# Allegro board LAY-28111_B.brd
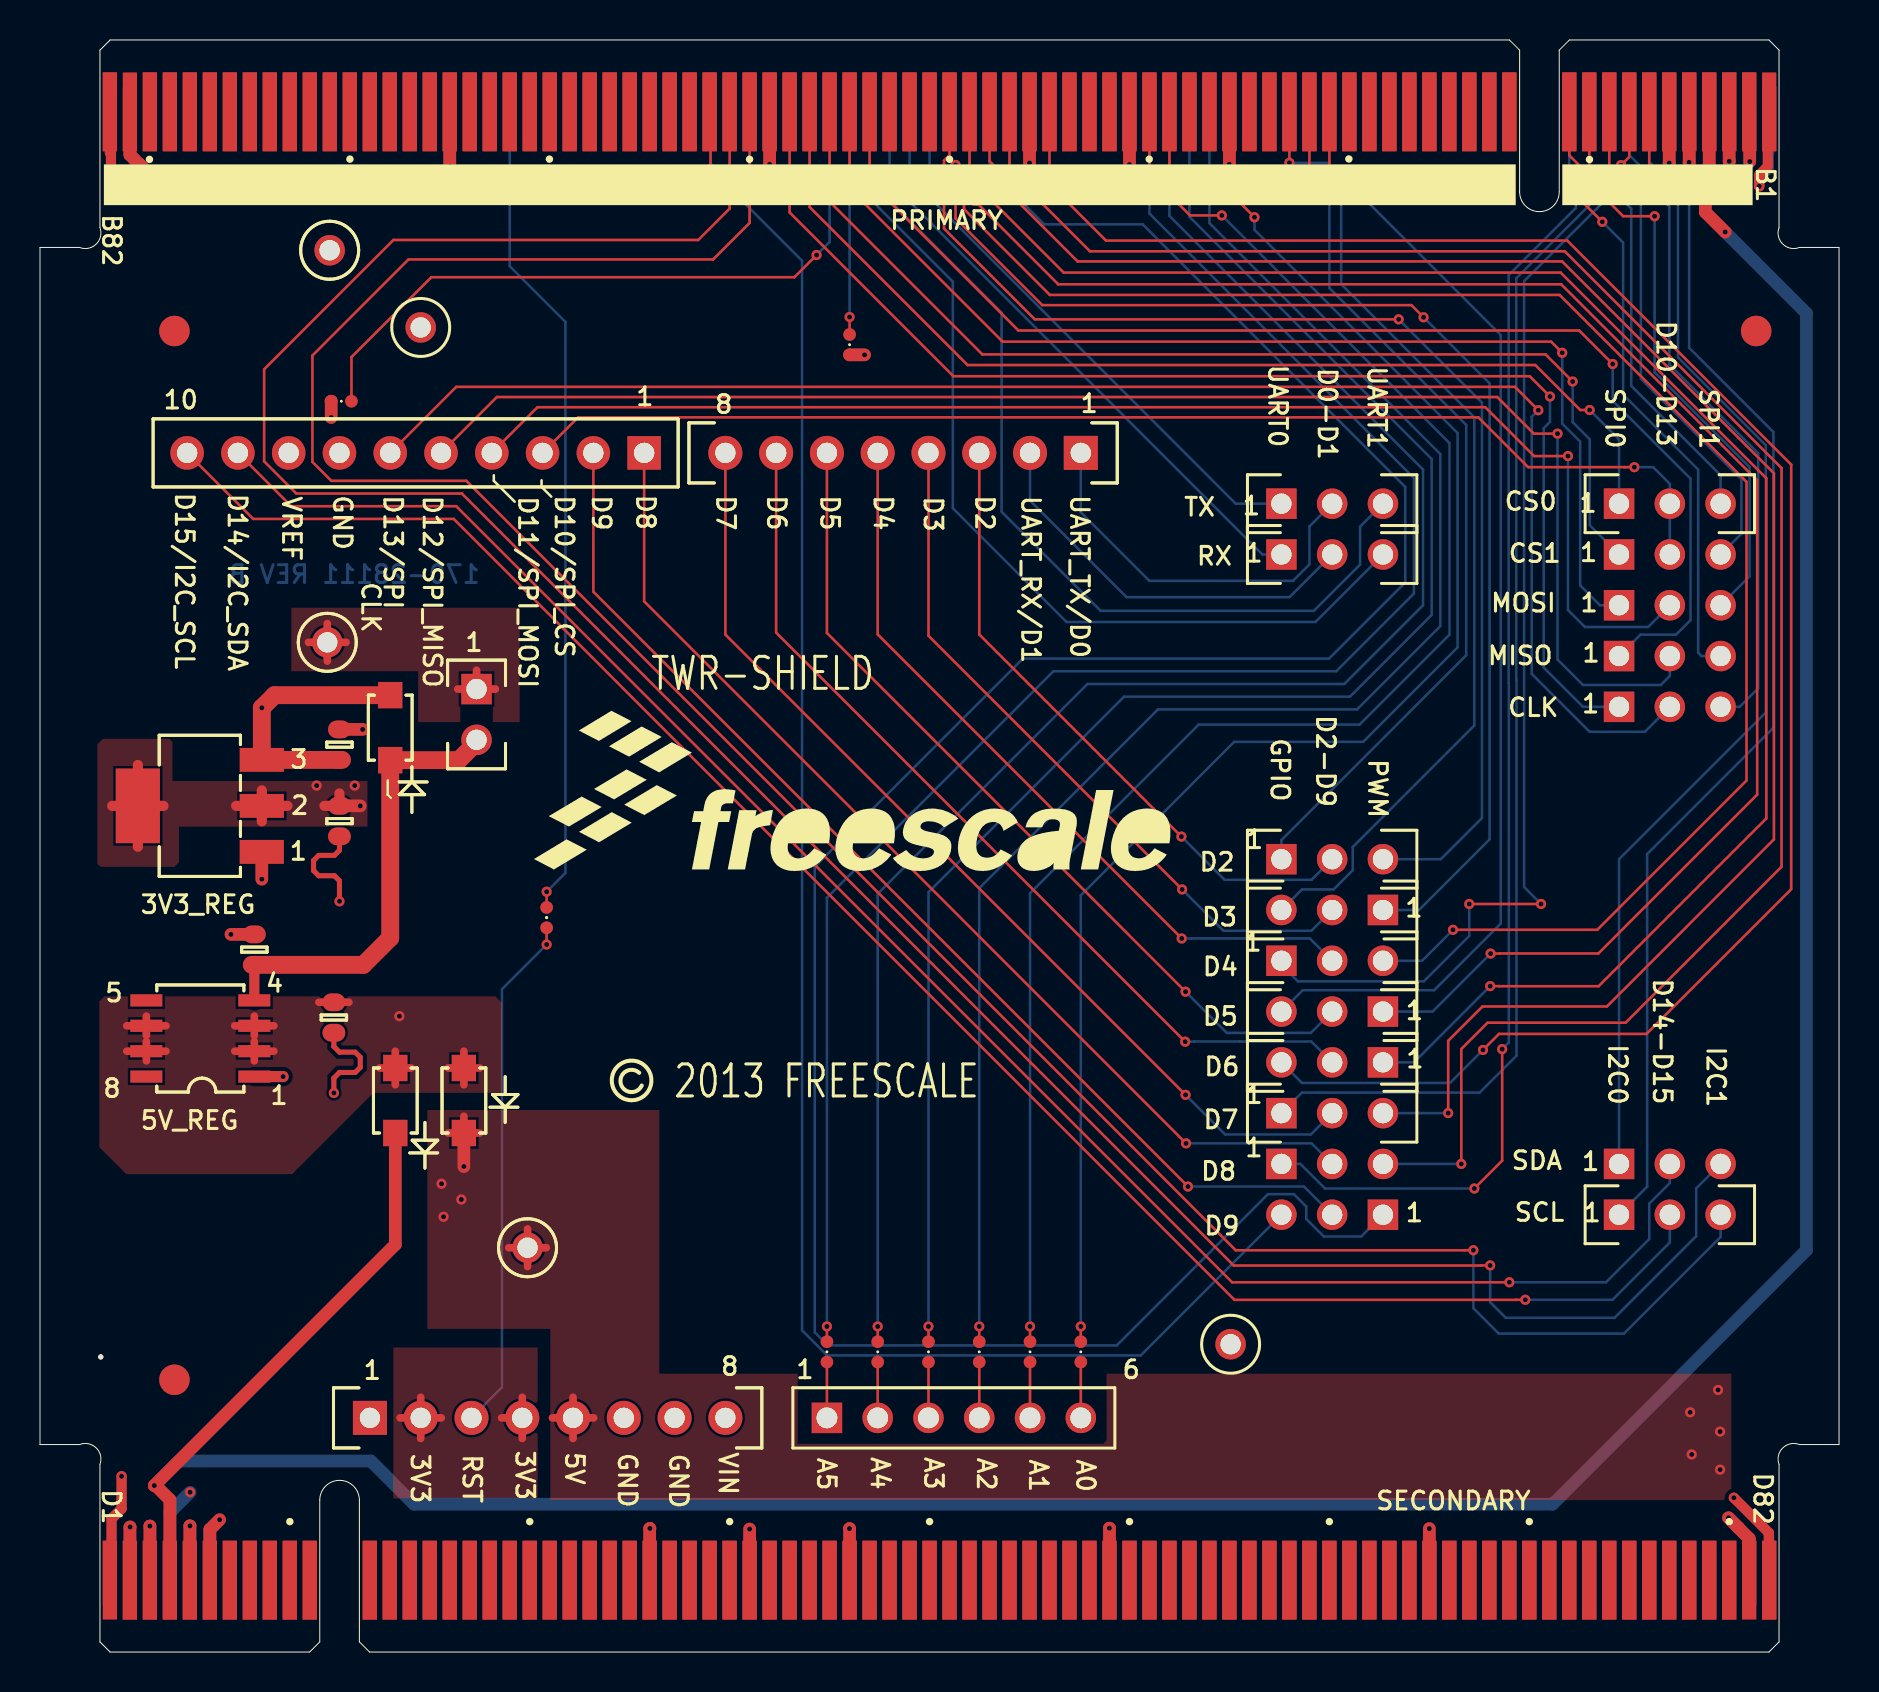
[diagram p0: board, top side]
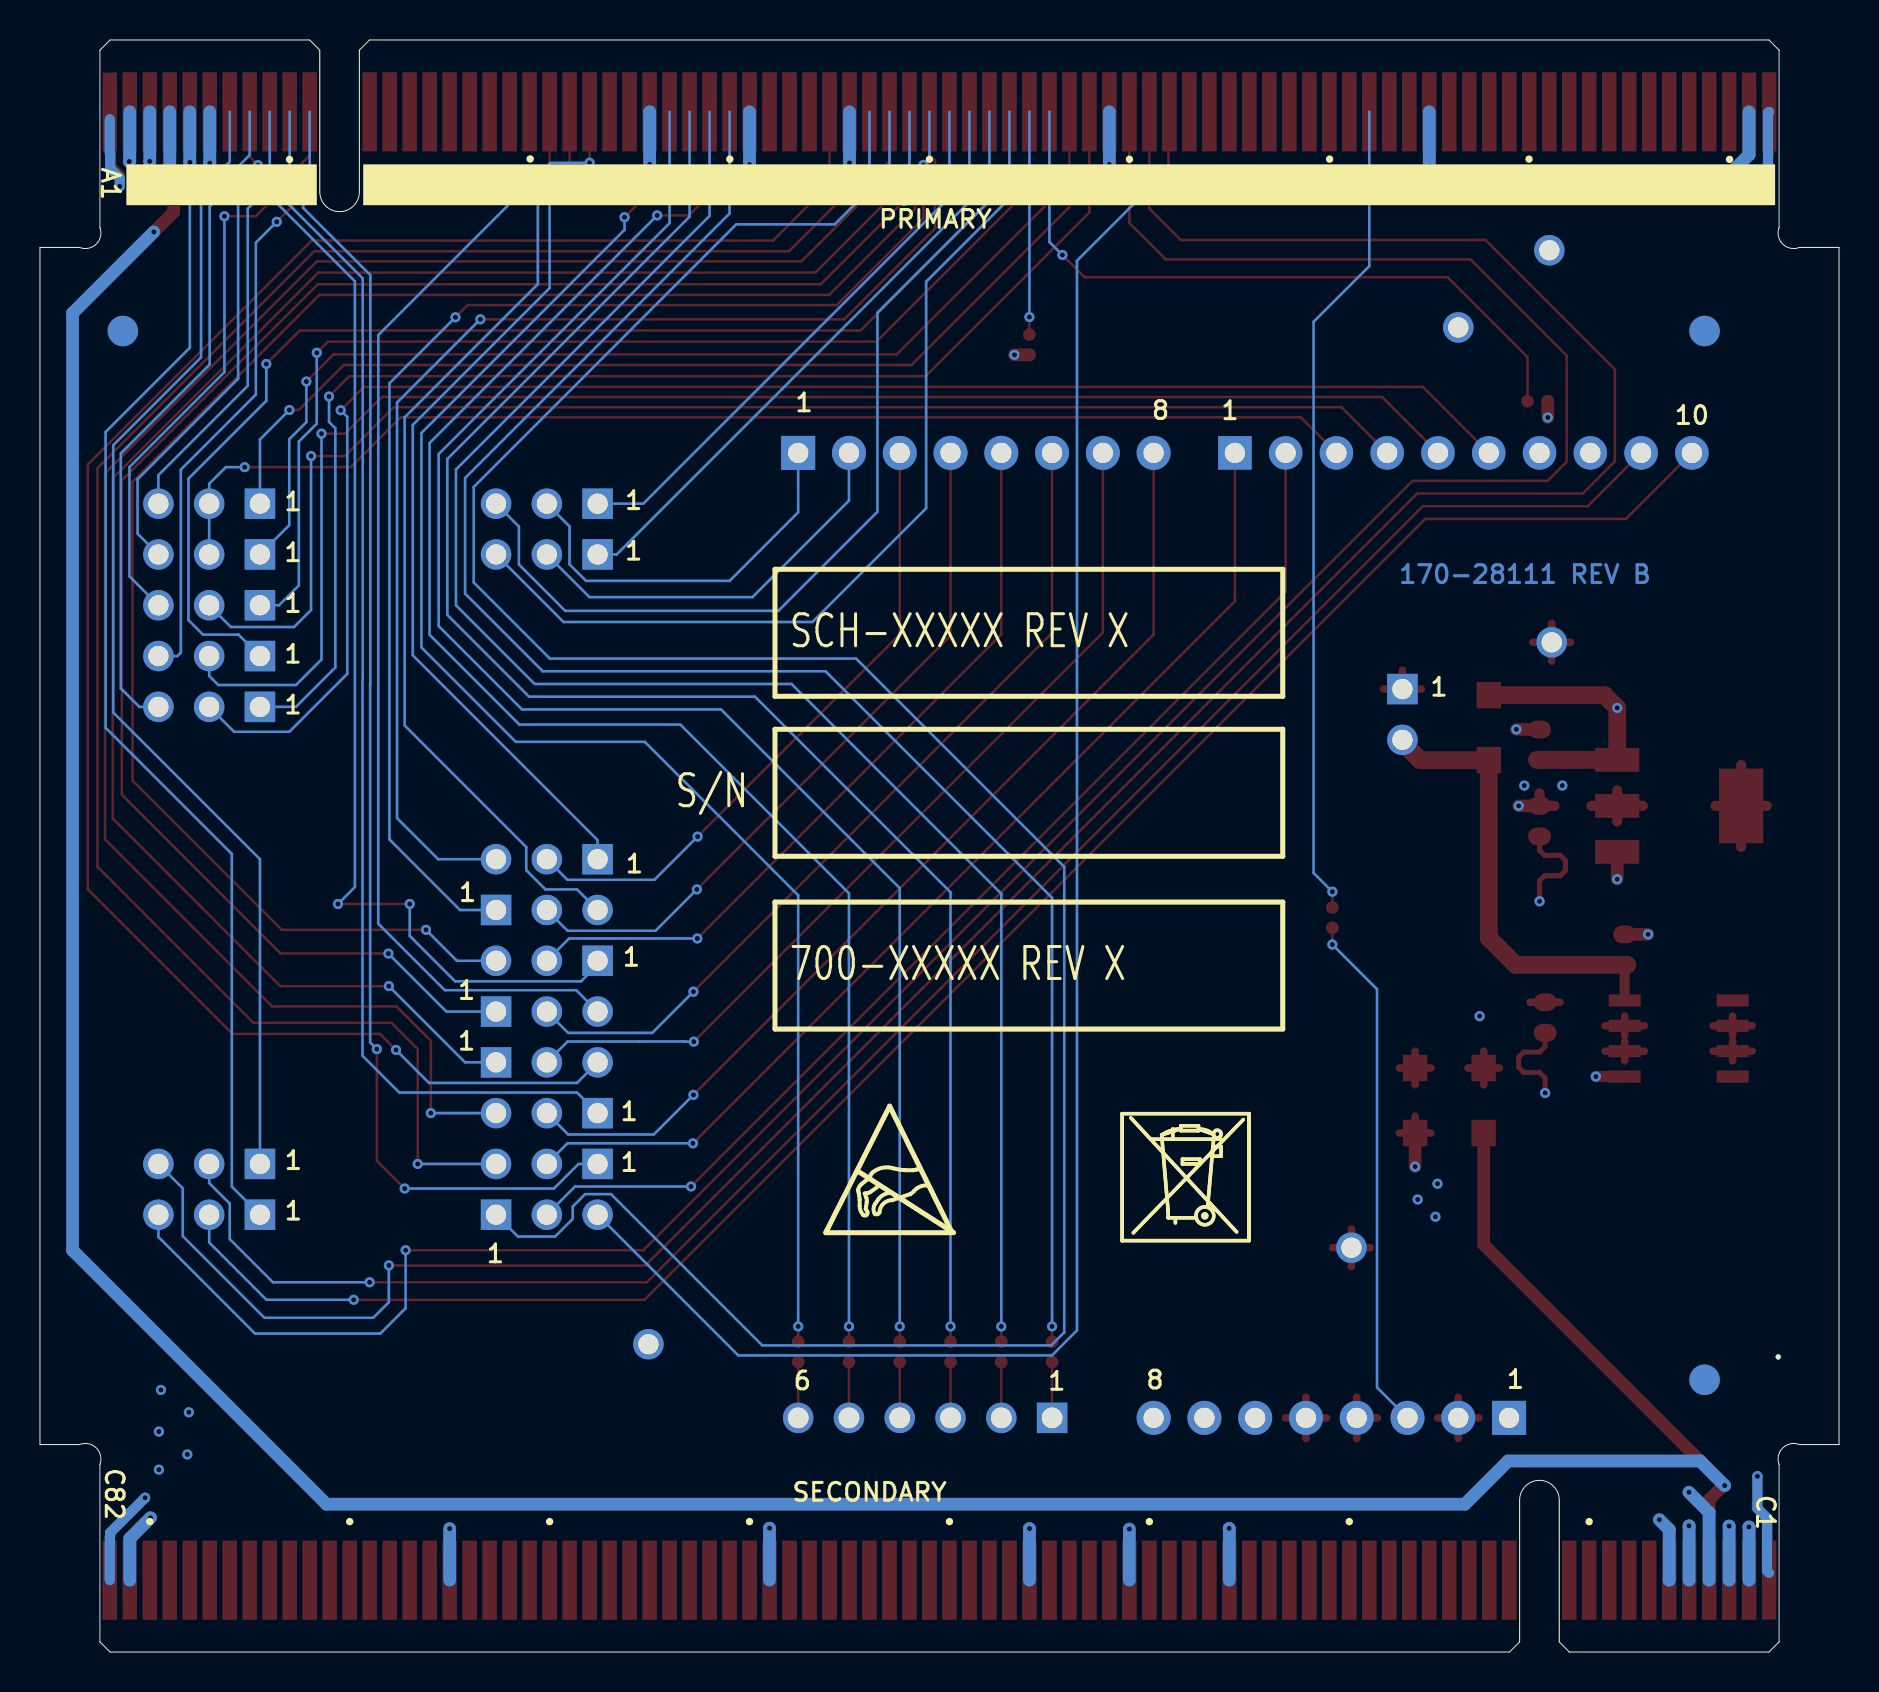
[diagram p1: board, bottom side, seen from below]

Outline 89.99 x 80.62 mm; copper layers: TOP, L2_GND, L3_PWR, BOTTOM. Coordinates in mm from the lower left corner of the outline.
Outline path: 0,70.24 0,10.38 1.98,10.38 arc(2.82,10.21) 3,9.37 3,0.51 3.51,0 13.49,0 14,0.51 14,7.59 arc(14.99,8.59) 15.98,7.59 15.98,0.51 16.48,0 86.49,0 86.99,0.51 86.99,9.37 arc(87.18,10.21) 88.01,10.38 89.99,10.38 89.99,70.24 88.01,70.24 arc(87.18,70.41) 86.99,71.25 86.99,80.11 86.49,80.62 76.5,80.62 76,80.11 76,73.03 arc(75.01,72.03) 74.02,73.03 74.02,80.11 73.51,80.62 3.51,80.62 3,80.11 3,71.25 arc(2.82,70.41) 1.98,70.24 0,70.24

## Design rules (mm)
net group POWER: nets ELE_PS_SENSE GND VIN_HDR VIN_HDR_D

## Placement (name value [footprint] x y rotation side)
C2  10uF  [CC0603_OV]  14.98 41.55 270 top
C4  10uF  [CC0603_OV]  14.98 45.38 90 top
C5  10uF  [CC0603_OV]  14.7 31.73 270 top
C6  10uF  [CC0603_OV]  10.72 35.13 90 top
D12  MBR120VLSFT1G  [SOD-123]  17.52 46.23 90 top
D15  MBR120VLSFT1G  [SOD-123]  21.2 27.58 270 top
D16  MBR120VLSFT1G  [SOD-123]  17.77 27.58 270 top
J1  CON_1X8  [CON_1X8_SKT_2P54_TH]  52.06 59.97 270 top
J2  CON_1X10  [HDR110]  30.22 59.97 270 top
J3  CON_1X6  [CON_SKT1X6_TH]  39.36 11.71 90 top
J4  CON_1X8  [CON_1X8_SKT_2P54_TH]  16.5 11.71 90 top
J16  PCI EXPRESS TOWER SYSTEM  [CN2X82_FINGER_ASS]  3 14.76 0 top
J20  HDR 1X2 TH  [SH_HDR102_BOTTOM]  21.84 48.16 0 top
J63  HDR 1x3 TH  [HDR103_SHORT1_2]  62.1 54.89 90 top
J64  HDR 1x3 TH  [HDR103_SHORT1_2]  78.99 24.41 90 top
J65  HDR 1x3 TH  [HDR103_SHORT1_2]  78.99 47.27 90 top
J66  HDR 1x3 TH  [HDR103_SHORT1_2]  78.99 21.87 90 top
J67  HDR 1x3 TH  [HDR103_SHORT1_2]  62.1 57.43 90 top
J68  HDR 1x3 TH  [HDR103_SHORT1_2]  67.18 37.11 270 top
J69  HDR 1x3 TH  [HDR103_SHORT1_2]  62.1 34.57 90 top
J70  HDR_1X3  [HDR103]  78.99 54.89 90 top
J71  HDR 1x3 TH  [HDR103_SHORT1_2]  67.18 21.87 270 top
J72  HDR 1x3 TH  [HDR103_SHORT1_2]  62.1 39.65 90 top
J73  HDR 1x3 TH  [HDR103_SHORT1_2]  78.99 52.35 90 top
J74  HDR 1x3 TH  [HDR103_SHORT1_2]  78.99 57.43 90 top
J78  HDR 1x3 TH  [HDR103_SHORT1_2]  67.18 32.03 270 top
J80  HDR 1x3 TH  [HDR103_SHORT1_2]  67.18 29.49 270 top
J81  HDR 1x3 TH  [HDR103_SHORT1_2]  78.99 49.81 90 top
J82  HDR 1x3 TH  [HDR103_SHORT1_2]  62.1 24.41 90 top
J83  HDR 1x3 TH  [HDR103_SHORT1_2]  62.1 26.95 90 top
NOREF  -  [unnamed]  3.04 14.76 0 top
NOREF#2  -  [#2]  5.02 37.18 0 top
NOREF#3  -  [#2]  51.86 -0.01 0 top
NOREF#4  -  [unnamed]  6.73 66.07 0 top
NOREF#5  -  [#2]  4.54 3.59 0 top
NOREF#6  -  [#2]  27.68 59.97 0 top
NOREF#7  -  [#2]  50.67 130.33 0 top
NOREF#8  -  [unnamed]  6.73 13.61 0 top
NOREF#9  -  [#2]  -93.48 -190.35 0 top
NOREF#10  -  [#2]  -3.94 -37.31 0 top
NOREF#11  -  [#2]  29.72 28.71 0 top
NOREF#12  -  [#2]  24.71 39.55 0 top
NOREF#13  -  [#2]  -88.4 146.2 0 top
NOREF#14  -  [#2]  0.05 70.23 0 top
NOREF#15  -  [#2]  87.04 80.11 0 top
NOREF#16  -  [#2]  10.72 28.78 90 top
NOREF#17  -  [#2]  5.32 28.78 0 top
NOREF#18  -  [#2]  35.1 80.63 0 top
NOREF#19  -  [#2]  0.05 10.39 90 top
NOREF#20  -  [#2]  -409.71 -287.38 0 top
NOREF#21  -  [#2]  10.02 33.18 90 top
NOREF#22  -  [#2]  0.05 10.38 90 top
NOREF#23  -  [#2]  90.04 10.38 90 top
NOREF#24  -  [#2]  0.05 10.39 90 top
NOREF#25  -  [#2]  3.04 14.76 0 top
NOREF#26  -  [#2]  86.53 0 90 top
NOREF#27  -  [#2]  16.02 0.51 0 top
NOREF#28  -  [#2]  0.05 10.39 90 top
NOREF#29  -  [#2]  184.91 70.26 0 top
NOREF#30  -  [#2]  0.05 10.39 0 top
NOREF#31  -  [#2]  141.23 79.22 0 top
NOREF#32  -  [unnamed]  85.85 66.07 0 top
NOREF#33  -  [#2]  3.04 14.76 0 top
NOREF#34  -  [#2]  75.06 88.58 0 top
NOREF#35  -  [#2]  0.05 10.39 90 top
NOREF#36  -  [#2]  200.15 4.85 0 top
NOREF#37  -  [#2]  79.88 10.95 0 top
NOREF#38  -  [#2]  5.54 77.03 0 top
NOREF#39  -  [#2]  168.27 -55.73 0 top
NOREF#40  -  [#2]  3.04 0.51 0 top
NOREF#41  -  [#2]  -378.59 230.02 0 top
NOREF#42  -  [#2]  2.27 15.54 0 top
NOREF#43  -  [#2]  3.55 0 90 top
NOREF#44  -  [unnamed]  85.85 66.07 180 bottom
NOREF#45  -  [#2]  53.23 39.8 180 bottom
NOREF#46  -  [#2]  50.67 20.97 180 bottom
NOREF#47  -  [unnamed]  6.73 66.07 180 bottom
NOREF#48  -  [#2]  35.86 20.57 180 bottom
NOREF#49  -  [unnamed]  6.73 13.61 180 bottom
NOREF#50  -  [#2]  53.23 31.16 180 bottom
NOREF#51  -  [#2]  53.23 47.8 180 bottom
NOREF#52  -  [#2]  79.88 10.95 180 bottom
R78  0  [RC0402_25]  15.07 62.55 180 top
R79  0  [RC0402_25]  25.34 36.73 270 top
R80  0  [RC0402_25]  46.98 15.01 270 top
R81  0  [RC0402_25]  44.44 15.01 270 top
R82  0  [RC0402_25]  41.9 15.01 270 top
R83  0  [RC0402_25]  39.36 15.01 270 top
R84  0  [RC0402_25]  52.06 15.01 90 top
R85  0  [RC0402_25]  49.52 15.01 90 top
R86  0  [RC0402_25]  40.5 65.38 270 top
TP1  TEST POINT WHITE  [TEST_LOOP]  24.39 20.22 0 top
TP2  TEST POINT WHITE  [TEST_LOOP]  14.37 50.5 0 top
TP3  TEST POINT WHITE  [TEST_LOOP]  14.49 70.1 0 top
TP4  TEST POINT WHITE  [TEST_LOOP]  59.56 15.39 0 top
TP5  TEST POINT WHITE  [TEST_LOOP]  19.04 66.24 0 top
U1  NCP1117ST33T3G  [SOT223]  8 42.32 90 top
U2  MC33269DR2-5.0G  [SO8_1P27_4X5]  8.02 30.68 180 top

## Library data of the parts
C2 C4-C6 = CAP_NP
D12 D15 D16 = DIODE_SCHTKY
J1 J4 = CONN_HDR_8X1
J2 = RCPT 1X10
J3 = CONN_HDR_6X1
J16 = CONN_PCI_XPRESS_X16_328P
J20 = CONN_HDR_2X1
J63-J69 J71-J74 J78 J80-J83 = CONN_HDR_3X1_SHORT
J70 = CONN_HDR_3X1
R78-R86 = RES
TP1-TP5 = TestLoop
U1 = LD1117AS18
U2 = MC33269D

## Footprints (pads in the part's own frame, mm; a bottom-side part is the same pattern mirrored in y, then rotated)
CC0603_OV
  oval 0.889x1.143 smd: 1(-0.762,0) 2(0.762,0)
CN2X82_FINGER_ASS
  rect 0.711x3.2 smd: A1(83.499,61.9) B81(1.499,61.9) C1(0.499,-10.795) D81(82.499,-10.795)
  rect 0.711x3.937 smd: A2(82.499,62.268) A3(81.499,62.268) A4(80.499,62.268) A5(79.499,62.268) A6(78.499,62.268) A7(77.499,62.268) A8(76.499,62.268) A9(75.499,62.268) A10(74.499,62.268) A11(73.499,62.268) A12(70.499,62.268) A13(69.499,62.268) A14(68.499,62.268) A15(67.499,62.268) A16(66.499,62.268) A17(65.499,62.268) A18(64.499,62.268) A19(63.499,62.268) A20(62.499,62.268) A21(61.499,62.268) A22(60.499,62.268) A23(59.499,62.268) A24(58.499,62.268) A25(57.499,62.268) A26(56.499,62.268) A27(55.499,62.268) A28(54.499,62.268) A29(53.499,62.268) A30(52.499,62.268) A31(51.499,62.268) A32(50.499,62.268) A33(49.499,62.268) A34(48.499,62.268) A35(47.499,62.268) A36(46.499,62.268) A37(45.499,62.268) A38(44.499,62.268) A39(43.499,62.268) A40(42.499,62.268) A41(41.499,62.268) A42(40.499,62.268) A43(39.499,62.268) A44(38.499,62.268) A45(37.499,62.268) A46(36.499,62.268) A47(35.499,62.268) A48(34.499,62.268) A49(33.499,62.268) A50(32.499,62.268) A51(31.499,62.268) A52(30.499,62.268) A53(29.499,62.268) A54(28.499,62.268) A55(27.499,62.268) A56(26.499,62.268) A57(25.499,62.268) A58(24.499,62.268) A59(23.499,62.268) A60(22.499,62.268) A61(21.499,62.268) A62(20.499,62.268) A63(19.499,62.268) A64(18.499,62.268) A65(17.499,62.268) A66(16.499,62.268) A67(15.499,62.268) A68(14.499,62.268) A69(13.499,62.268) A70(12.499,62.268) A71(11.499,62.268) A72(10.499,62.268) A73(9.499,62.268) A74(8.499,62.268) A75(7.499,62.268) A76(6.499,62.268) A77(5.499,62.268) A78(4.499,62.268) A79(3.499,62.268) A80(2.499,62.268) A81(1.499,62.268) A82(0.499,62.268) B1(83.499,62.268) B2(82.499,62.268) B3(81.499,62.268) B4(80.499,62.268) B5(79.499,62.268) B6(78.499,62.268) B7(77.499,62.268) B8(76.499,62.268) B9(75.499,62.268) B10(74.499,62.268) B11(73.499,62.268) B12(70.499,62.268) B13(69.499,62.268) B14(68.499,62.268) B15(67.499,62.268) B16(66.499,62.268) B17(65.499,62.268) B18(64.499,62.268) B19(63.499,62.268) B20(62.499,62.268) B21(61.499,62.268) B22(60.499,62.268) B23(59.499,62.268) B24(58.499,62.268) B25(57.499,62.268) B26(56.499,62.268) B27(55.499,62.268) B28(54.499,62.268) B29(53.499,62.268) B30(52.499,62.268) B31(51.499,62.268) B32(50.499,62.268) B33(49.499,62.268) B34(48.499,62.268) B35(47.499,62.268) B36(46.499,62.268) B37(45.499,62.268) B38(44.499,62.268) B39(43.499,62.268) B40(42.499,62.268) B41(41.499,62.268) B42(40.499,62.268) B43(39.499,62.268) B44(38.499,62.268) B45(37.499,62.268) B46(36.499,62.268) B47(35.499,62.268) B48(34.499,62.268) B49(33.499,62.268) B50(32.499,62.268) B51(31.499,62.268) B52(30.499,62.268) B53(29.499,62.268) B54(28.499,62.268) B55(27.499,62.268) B56(26.499,62.268) B57(25.499,62.268) B58(24.499,62.268) B59(23.499,62.268) B60(22.499,62.268) B61(21.499,62.268) B62(20.499,62.268) B63(19.499,62.268) B64(18.499,62.268) B65(17.499,62.268) B66(16.499,62.268) B67(15.499,62.268) B68(14.499,62.268) B69(13.499,62.268) B70(12.499,62.268) B71(11.499,62.268) B72(10.499,62.268) B73(9.499,62.268) B74(8.499,62.268) B75(7.499,62.268) B76(6.499,62.268) B77(5.499,62.268) B78(4.499,62.268) B79(3.499,62.268) B80(2.499,62.268) B82(0.499,62.268) C2(1.499,-11.163) C3(2.499,-11.163) C4(3.499,-11.163) C5(4.499,-11.163) C6(5.499,-11.163) C7(6.499,-11.163) C8(7.499,-11.163) C9(8.499,-11.163) C10(9.499,-11.163) C11(10.499,-11.163) C12(13.499,-11.163) C13(14.499,-11.163) C14(15.499,-11.163) C15(16.499,-11.163) C16(17.499,-11.163) C17(18.499,-11.163) C18(19.499,-11.163) C19(20.499,-11.163) C20(21.499,-11.163) C21(22.499,-11.163) C22(23.499,-11.163) C23(24.499,-11.163) C24(25.499,-11.163) C25(26.499,-11.163) C26(27.499,-11.163) C27(28.499,-11.163) C28(29.499,-11.163) C29(30.499,-11.163) C30(31.499,-11.163) C31(32.499,-11.163) C32(33.499,-11.163) C33(34.499,-11.163) C34(35.499,-11.163) C35(36.499,-11.163) C36(37.499,-11.163) C37(38.499,-11.163) C38(39.499,-11.163) C39(40.499,-11.163) C40(41.499,-11.163) C41(42.499,-11.163) C42(43.499,-11.163) C43(44.499,-11.163) C44(45.499,-11.163) C45(46.499,-11.163) C46(47.499,-11.163) C47(48.499,-11.163) C48(49.499,-11.163) C49(50.499,-11.163) C50(51.499,-11.163) C51(52.499,-11.163) C52(53.499,-11.163) C53(54.499,-11.163) C54(55.499,-11.163) C55(56.499,-11.163) C56(57.499,-11.163) C57(58.499,-11.163) C58(59.499,-11.163) C59(60.499,-11.163) C60(61.499,-11.163) C61(62.499,-11.163) C62(63.499,-11.163) C63(64.499,-11.163) C64(65.499,-11.163) C65(66.499,-11.163) C66(67.499,-11.163) C67(68.499,-11.163) C68(69.499,-11.163) C69(70.499,-11.163) C70(71.499,-11.163) C71(72.499,-11.163) C72(73.499,-11.163) C73(74.499,-11.163) C74(75.499,-11.163) C75(76.499,-11.163) C76(77.499,-11.163) C77(78.499,-11.163) C78(79.499,-11.163) C79(80.499,-11.163) C80(81.499,-11.163) C81(82.499,-11.163) C82(83.499,-11.163) D1(0.499,-11.163) D2(1.499,-11.163) D3(2.499,-11.163) D4(3.499,-11.163) D5(4.499,-11.163) D6(5.499,-11.163) D7(6.499,-11.163) D8(7.499,-11.163) D9(8.499,-11.163) D10(9.499,-11.163) D11(10.499,-11.163) D12(13.499,-11.163) D13(14.499,-11.163) D14(15.499,-11.163) D15(16.499,-11.163) D16(17.499,-11.163) D17(18.499,-11.163) D18(19.499,-11.163) D19(20.499,-11.163) D20(21.499,-11.163) D21(22.499,-11.163) D22(23.499,-11.163) D23(24.499,-11.163) D24(25.499,-11.163) D25(26.499,-11.163) D26(27.499,-11.163) D27(28.499,-11.163) D28(29.499,-11.163) D29(30.499,-11.163) D30(31.499,-11.163) D31(32.499,-11.163) D32(33.499,-11.163) D33(34.499,-11.163) D34(35.499,-11.163) D35(36.499,-11.163) D36(37.499,-11.163) D37(38.499,-11.163) D38(39.499,-11.163) D39(40.499,-11.163) D40(41.499,-11.163) D41(42.499,-11.163) D42(43.499,-11.163) D43(44.499,-11.163) D44(45.499,-11.163) D45(46.499,-11.163) D46(47.499,-11.163) D47(48.499,-11.163) D48(49.499,-11.163) D49(50.499,-11.163) D50(51.499,-11.163) D51(52.499,-11.163) D52(53.499,-11.163) D53(54.499,-11.163) D54(55.499,-11.163) D55(56.499,-11.163) D56(57.499,-11.163) D57(58.499,-11.163) D58(59.499,-11.163) D59(60.499,-11.163) D60(61.499,-11.163) D61(62.499,-11.163) D62(63.499,-11.163) D63(64.499,-11.163) D64(65.499,-11.163) D65(66.499,-11.163) D66(67.499,-11.163) D67(68.499,-11.163) D68(69.499,-11.163) D69(70.499,-11.163) D70(71.499,-11.163) D71(72.499,-11.163) D72(73.499,-11.163) D73(74.499,-11.163) D74(75.499,-11.163) D75(76.499,-11.163) D76(77.499,-11.163) D77(78.499,-11.163) D78(79.499,-11.163) D79(80.499,-11.163) D80(81.499,-11.163) D82(83.499,-11.163)
CON_1X8_SKT_2P54_TH
  rect 1.702x1.702 hole 1.016: 1(0,0)
  round 1.702 hole 1.016: 2(0,-2.54) 3(0,-5.08) 4(0,-7.62) 5(0,-10.16) 6(0,-12.7) 7(0,-15.24) 8(0,-17.78)
CON_SKT1X6_TH
  rect 1.524x1.524 hole 1.041: 1(0,0)
  round 1.524 hole 1.041: 2(0,-2.54) 3(0,-5.08) 4(0,-7.62) 5(0,-10.16) 6(0,-12.7)
HDR103
  rect 1.524x1.524 hole 1.016: 1(0,0)
  round 1.524 hole 1.016: 2(0,-2.54) 3(0,-5.08)
HDR103_SHORT1_2
  rect 1.524x1.524 hole 1.016: 1(0,0)
  round 1.524 hole 1.016: 2(0,-2.54) 3(0,-5.08)
HDR110
  rect 1.676x1.676 hole 1.016: 1(0,0)
  round 1.676 hole 1.016: 2(0,-2.54) 3(0,-5.08) 4(0,-7.62) 5(0,-10.16) 6(0,-12.7) 7(0,-15.24) 8(0,-17.78) 9(0,-20.32) 10(0,-22.86)
RC0402_25
  round 0.635 smd: 1(-0.508,0) 2(0.508,0)
SH_HDR102_BOTTOM
  rect 1.524x1.524 hole 1.016: 1(0,0)
  round 1.524 hole 1.016: 2(0,-2.54)
SO8_1P27_4X5
  rect 1.6x0.61 smd: 1(-2.7,1.905) 2(-2.7,0.635) 3(-2.7,-0.635) 4(-2.7,-1.905) 5(2.7,-1.905) 6(2.7,-0.635) 7(2.7,0.635) 8(2.7,1.905)
SOD-123
  rect 1.321x1.219 smd: A(-1.626,0) C(1.626,0)
SOT223
  rect 1.194x2.21 smd: 1(-2.3,-3.1) 2(0,-3.1) 3(2.3,-3.1)
  rect 3.734x2.21 smd: 4(0,3.1)
TEST_LOOP
  round 1.524 hole 1.016: 1(0,0)
unnamed
  round 0.254 hole 0.635 unplated: (0,0)

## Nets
3V3_ELEV: C2.1 J4.2 J4.4 J16.A3(3.3V_4) J16.A4(3.3V_5) J16.A36(3.3V_6) J16.A82(3.3V_7) J16.B3(3.3V_1) J16.B36(3.3V_2) J16.B82(3.3V_3) J16.C3(3.3V_11) J16.C4(3.3V_12) J16.C36(3.3V_13) J16.C82(3.3V_14) J16.D3(3.3V_8) J16.D36(3.3V_9) J16.D82(3.3V_10) TP3.1(PIN1) U1.2(VOUT) U1.4(TAB)
5V_ELEV: D15.C J4.5 J16.A1(5V_2) J16.B1(5V_1) J16.C1(5V_4) J16.D1(5V_3) TP1.1(PIN1)
GND: C2.2 C4.2 C5.2 C6.2 J2.7 J4.6 J4.7 J16.A2(GND_9) J16.A5(GND_10) J16.A6(GND_11) J16.A26(GND_12) J16.A31(GND_13) J16.A49(GND_14) J16.A65(GND_15) J16.A81(GND_16) J16.B2(GND_1) J16.B5(GND_2) J16.B6(GND_3) J16.B26(GND_4) J16.B31(GND_5) J16.B49(GND_6) J16.B65(GND_7) J16.B81(GND_8) J16.C2(GND_25) J16.C5(GND_26) J16.C6(GND_27) J16.C26(GND_28) J16.C31(GND_29) J16.C49(GND_30) J16.C65(GND_31) J16.C81(GND_32) J16.D2(GND_17) J16.D5(GND_18) J16.D6(GND_19) J16.D26(GND_20) J16.D31(GND_21) J16.D49(GND_22) J16.D65(GND_23) J16.D81(GND_24) R86.2 TP4.1(PIN1) U1.1(GND) U2.1(GND/ADJ)
P5V_VREG: C5.1 D15.A D16.A U2.2(VOUT1) U2.3(VOUT2) U2.6(VOUT3) U2.7(VOUT4)
VIN: J4.8 J20.1 TP2.1(PIN1)
VIN_HDR: C6.1 D12.A J20.2 U2.4(VIN)
VIN_HDR_D: C4.1 D12.C U1.3(VIN)
A0: J3.1 R83.2
A1: J3.2 R82.2
A2: J3.3 R81.2
A3: J3.4 R80.2
A4: J3.5 R85.1
A5: J3.6 R84.1
D2: J1.3 J72.2
D3: J1.4 J68.2
D4: J1.5 J69.2
D5: J1.6 J78.2
D6: J1.7 J80.2
D7: J1.8 J83.2
D8: J2.1 J82.2
D9: J2.2 J71.2
D10/SPI_CS: J2.3 J70.2 J74.2
D11/SPI_MOSI: J2.4 J73.2
D12/SPI_MISO: J2.5 J81.2
D13/SPI_CLK: J2.6 J65.2
D14/I2C_SDA: J2.9 J64.2
D15/I2C_SCL: J2.10 J66.2
ELE_PS_SENSE: D16.C J16.B4(ELE_PS_SENSE_1) J16.D4(ELE_PS_SENSE_2)
GPIO/D2: J16.B21(GPIO1/UART1_RTS) J72.1
GPIO/D3: J16.B22(GPIO2/SDHC_D1) J68.3
GPIO/D4: J16.A9(GPIO9/UART1_CTS) J69.1
GPIO/D5: J16.B23(GPIO3) J78.3
GPIO/D6: J16.B35(GPIO4) J80.3
GPIO/D7: J16.A10(GPIO8/SDHC_D2) J83.1
GPIO/D8: J16.A11(GPIO7/SD_WP_DET) J82.1
GPIO/D9: J16.B52(GPIO5/SPI0_HOLD/IO3) J71.3
I2C0_SCL/D15: J16.A7(I2C0_SCL) J66.1
I2C0_SDA/D14: J16.A8(I2C0_SDA) J64.1
I2C1_SCL/D15: J16.B50(I2C1_SCL) J66.3
I2C1_SDA/D14: J16.B51(I2C1_SDA) J64.3
PWM/D2: J16.B40(PWM4) J72.3
PWM/D3: J16.A40(PWM0) J68.1
PWM/D4: J16.B39(PWM5) J69.3
PWM/D5: J16.A39(PWM1) J78.1
PWM/D6: J16.A38(PWM2) J80.1
PWM/D7: J16.B38(PWM6) J83.3
PWM/D8: J16.B37(PWM7) J82.3
PWM/D9: J16.A37(PWM3) J71.1
RESET_B: J4.3 R79.2
SPI0_CS0/D10: J16.B47(S\P\I\0\_\C\S\1\) J74.1
SPI0_CS1/D10: J16.B46(S\P\I\0\_\C\S\0\) J70.1
SPI0_MISO/D12: J16.B44(SPI0_MISO/IO1) J81.1
SPI0_MOSI/D11: J16.B45(SPI0_MOSI/IO0) J73.1
SPI0_SCK/D13: J16.B48(SPI0_CLK) J65.1
SPI1_CS0/D10: J16.B9(SDHC_D3/S\P\I\1\_\C\S\0\) J74.3
SPI1_CS1/D10: J16.B8(SDHC_D3/S\P\I\1\_\C\S\1\) J70.3
SPI1_MISO/D12: J16.B11(SDHC_D0/SPI1_MISO) J81.3
SPI1_MOSI/D11: J16.B10(SDHC_CMD/SPI1_MOSI) J73.3
SPI1_SCK/D13: J16.B7(SDHC_CLK/SPI1_CLK) J65.3
UART0_RX/D0: J16.A41(UART0_RX) J67.1
UART0_TX/D1: J16.A42(UART0_TX) J63.1
UART1_RX/D0: J16.A43(UART1_RX) J67.3
UART1_TX/D1: J16.A44(UART1_TX) J63.3
UART_RX/D1: J1.2 J63.2
UART_TX/D0: J1.1 J67.2
VREF: J2.8 R78.2 TP5.1(PIN1)
N13251626: J16.B29(AN5) R84.2
N13251632: J16.B30(AN4) R85.2
N13255265: J16.A27(AN3) R80.1
N13255295: J16.A28(AN2) R81.1
N13255352: J16.A29(AN1) R82.1
N13255371: J16.A30(AN0) R83.1
N13256362: J16.A46(VDDA) R78.1
N13260720: J16.A62(R\S\T\I\N\) R79.1
N13275722: J16.A45(VSSA) R86.1

Pads without a net: J4 1; J16 A12 A13 A14 A15 A16 A17 A18 A19 A20 A21 A22 A23 A24 A25 A32 A33 A34 A35 A47 A48 A50 A51 A52 A53 A54 A55 A56 A57 A58 A59 A60 A61 A63 A64 A66 A67 A68 A69 A70 A71 A72 A73 A74 A75 A76 A77 A78 A79 A80 B12 B13 B14 B15 B16 B17 B18 B19 B20 B24 B25 B27 B28 B32 B33 B34 B41 B42 B43 B53 B54 B55 B56 B57 B58 B59 B60 B61 B62 B63 B64 B66 B67 B68 B69 B70 B71 B72 B73 B74 B75 B76 B77 B78 B79 B80 C7 C8 C9 C10 C11 C12 C13 C14 C15 C16 C17 C18 C19 C20 C21 C22 C23 C24 C25 C27 C28 C29 C30 C32 C33 C34 C35 C37 C38 C39 C40 C41 C42 C43 C44 C45 C46 C47 C48 C50 C51 C52 C53 C54 C55 C56 C57 C58 C59 C60 C61 C62 C63 C64 C66 C67 C68 C69 C70 C71 C72 C73 C74 C75 C76 C77 C78 C79 C80 D7 D8 D9 D10 D11 D12 D13 D14 D15 D16 D17 D18 D19 D20 D21 D22 D23 D24 D25 D27 D28 D29 D30 D32 D33 D34 D35 D37 D38 D39 D40 D41 D42 D43 D44 D45 D46 D47 D48 D50 D51 D52 D53 D54 D55 D56 D57 D58 D59 D60 D61 D62 D63 D64 D66 D67 D68 D69 D70 D71 D72 D73 D74 D75 D76 D77 D78 D79 D80; U2 5 8

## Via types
v1: diameter 0.508, hole 0.254, TOP to BOTTOM, 107 vias

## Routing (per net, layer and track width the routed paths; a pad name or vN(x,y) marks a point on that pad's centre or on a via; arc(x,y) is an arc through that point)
3V3_ELEV: length 76.8
  TOP w0.381: 19.04,10.68 J4.2 ; J4.2 19.04,12.74 ; J4.2 20.07,11.71 ; J4.2 18.02,11.71 ; 24.12,10.68 J4.4 ; J4.4 23.1,11.71 ; J4.4 24.12,12.74
  TOP w0.508: 3.61,42.32 U1.4 ; U1.4 4.9,40.27 ; U1.4 6.18,42.32 ; U1.4 4.9,44.36 ; U1.2 11.1,43.09 ; U1.2 12.38,42.32 ; U1.2 11.1,41.54 ; U1.2 9.81,42.32 ; J16.C82 86.5,5.11 86.48,5.15 86.48,5.97 v1(84.73,7.71) ; v1(4.67,73.03) 3.55,74.15 3.55,74.93 3.5,74.99 J16.A82 ; 14.23,42.32 C2.1 14.98,42.94
  TOP w0.635: v1(84.5,74.55) 84.5,74.56 J16.A3 ; J16.C36 40.5,6.17 v1(40.49,6.17) ; v1(5.5,6.3) 5.5,6.3 J16.C3 ; v1(16.02,42.32) C2.1 ; J16.A36 v1(49.5,74.47)
  L3_PWR w0.381: 18.02,11.71 J4.2 ; J4.2 19.04,10.68 ; J4.2 20.07,11.71 ; J4.2 19.04,12.74 ; TP3.1 14.49,71.04 ; TP3.1 13.55,70.1 ; TP3.1 15.43,70.1 ; TP3.1 14.49,69.16
  BOTTOM w0.508: J16.A82 3.55,76.97 3.55,74.15 v1(4.67,73.03) ; v1(84.73,7.71) 86.48,5.97 86.48,5.8 86.5,5.77 J16.C82
  BOTTOM w0.635: J16.C3 5.5,6.3 v1(5.5,6.3) ; J16.A36 v1(49.5,74.47) ; J16.A4 83.5,73.84 v1(84.39,72.95) ; J16.C4 6.5,6.98 v1(7.51,7.99) ; J16.A3 84.5,74.56 v1(84.5,74.55) ; J16.C36 40.5,6.17 v1(40.49,6.17)
  vias: v1(13.84,43.33) v1(15.74,43.33)
5V_ELEV: length 30
  TOP w0.381: J4.5 26.66,12.74 ; J4.5 25.64,11.71 ; J4.5 26.66,10.68 ; J4.5 27.69,11.71 ; D15.C 21.2,26.79 ; D15.C 21.99,25.96 ; D15.C 20.42,25.96 ; TP1.1 25.33,20.22 ; TP1.1 24.39,21.16 ; TP1.1 24.39,19.28 ; TP1.1 23.45,20.22
  TOP w0.508: J16.B1 86.43,76.96 86.43,74.3 86,73.87 v1(86,73.3) ; v1(4.08,8.79) 4.08,7.16 3.58,6.65 3.58,3.67 J16.D1
  TOP w0.635: D15.C v1(21.2,24.28)
  BOTTOM w0.508: v1(86,73.3) 86,73.71 86.48,74.19 86.48,74.93 86.5,74.95 J16.A1 ; v1(4.08,8.79) 4.08,7.18 3.6,6.7 3.6,4.07 J16.C1
  vias: v1(20.09,23.42) v1(20.19,21.77) v1(21.08,22.63) v1(82.54,11.99) v1(82.62,9.88) v1(83.94,13.11) v1(84.04,11.02) v1(84.04,9.12)
GND: length 119.9
  TOP w0.254: C2.2 14.98,40.09 14.73,39.84 13.94,39.84 13.69,39.59 13.69,39.08 13.94,38.82 14.73,38.82 14.98,38.57 v1(14.98,37.54) ; v1(14.7,27.96) 14.7,28.71 14.98,28.98 15.77,28.98 16.02,29.24 16.02,29.75 15.77,30 14.98,30 14.7,30.28 C5.2
  TOP w0.559: U2.1 v1(12.16,28.78)
  TOP w0.635: J16.C65 v1(69.5,6.17) ; J16.A6 v1(81.5,74.46) ; J16.C5 7.5,6.3 v1(7.5,6.31) ; v1(53.49,6.19) 53.5,6.19 J16.C49 ; C4.2 v1(16.14,46.14) ; J16.D81 85.5,5.67 84.96,6.21 84.96,6.22 v1(84.46,6.72) ; J16.C26 30.5,6.17 v1(30.51,6.18) ; J16.A49 v1(36.5,74.4) ; v1(59.49,74.4) 59.5,74.41 J16.A26 ; J16.A65 v1(20.5,74.3) ; J16.A31 v1(54.5,74.39) ; J16.B81 4.5,74.88 4.99,74.39 4.99,74.39 v1(5.48,73.9) ; J16.C2 4.5,6.24 v1(4.51,6.25) ; v1(82.49,74.5) 82.5,74.51 J16.A5 ; C6.2 v1(9.55,35.89) ; J16.A2 85.53,77 v1(85.53,74.54) ; J16.C31 v1(35.5,6.15) ; U1.1 v1(11.1,38.65) ; R86.2 v1(41.25,64.87) ; J16.C6 8.5,6.13 v1(8.99,6.62)
  L2_GND w0.381: J2.7 14.98,60.99 ; J2.7 13.96,59.97 ; J2.7 14.98,58.95 ; J2.7 16,59.97 ; J4.7 32.77,11.71 ; J4.7 31.74,10.68 ; J4.7 30.72,11.71 ; J4.7 31.74,12.74 ; TP4.1 60.5,15.39 ; TP4.1 59.56,16.33 ; TP4.1 59.56,14.45 ; TP4.1 58.62,15.39 ; J4.6 29.2,12.74 ; J4.6 30.23,11.71 ; J4.6 28.18,11.71 ; J4.6 29.2,10.68
  BOTTOM w0.635: J16.C26 30.5,6.17 v1(30.51,6.18) ; v1(53.49,6.19) 53.5,6.19 J16.C49 ; J16.C6 8.49,3.6 8.49,6.12 v1(8.99,6.62) ; v1(4.51,6.25) 4.5,6.24 J16.C2 ; J16.C5 7.5,6.3 v1(7.5,6.31) ; v1(85.53,74.54) 85.5,74.57 J16.A2 ; v1(5.48,73.9) 4.5,74.88 J16.A81 ; v1(81.5,74.46) 81.5,74.49 J16.A6 ; v1(69.5,6.17) J16.C65 ; J16.A26 59.49,77.02 v1(59.49,74.4) ; J16.A65 v1(20.5,74.3) ; J16.A49 v1(36.5,74.4) ; v1(82.49,74.5) 82.5,74.51 J16.A5 ; J16.A31 v1(54.5,74.39) ; J16.C81 85.5,5.68 v1(84.46,6.72) ; J16.C31 v1(35.5,6.15)
P5V_VREG: length 19.7
  TOP w0.381: U2.7 6.3,30.05 ; U2.7 5.32,30.53 ; U2.7 5.32,29.57 ; U2.7 4.34,30.05 ; D16.A 17.77,30.05 ; D16.A 18.56,29.21 ; D16.A 17.77,28.37 ; D16.A 16.99,29.21 ; U2.6 5.32,31.8 ; U2.6 6.3,31.32 ; U2.6 4.34,31.32 ; U2.6 5.32,30.84 ; U2.3 10.72,31.8 ; U2.3 11.7,31.32 ; U2.3 10.72,30.84 ; U2.3 9.74,31.32 ; U2.2 10.72,30.53 ; U2.2 10.72,29.57 ; U2.2 9.74,30.05 ; U2.2 11.7,30.05 ; 15.45,32.49 C5.1 13.95,32.49 ; D15.A 21.2,30.05 ; D15.A 20.42,29.21 ; D15.A 21.2,28.37 ; D15.A 21.99,29.21
  vias: v1(17.98,31.8)
VIN: length 17.3
  TOP w0.381: J20.1 21.84,49.1 ; J20.1 22.78,48.16 ; J20.1 20.9,48.16 ; 14.37,49.55 TP2.1 ; TP2.1 14.37,51.44 ; TP2.1 13.43,50.5 ; TP2.1 15.31,50.5
  L3_PWR w0.381: 34.28,10.68 J4.8 ; J4.8 33.26,11.71 ; J4.8 35.31,11.71 ; J4.8 34.28,12.74 ; J20.1 21.84,49.1 ; J20.1 20.9,48.16 ; J20.1 22.78,48.16 ; 13.43,50.5 TP2.1 ; TP2.1 15.31,50.5 ; TP2.1 14.37,49.55 ; TP2.1 14.37,51.44
VIN_HDR: length 22.8
  TOP w0.508: U2.4 C6.1
  TOP w0.889: C6.1 16.17,34.37 17.52,35.71 17.52,44.6 20.95,44.6 21.84,45.49 21.84,45.62
VIN_HDR_D: length 13.2
  TOP w0.889: C4.1 U1.3 v1(11.1,47.22) 11.73,47.85 D12.C
A0: length 2.8
  TOP w0.127: R83.2 J3.1
A1: length 2.8
  TOP w0.127: R82.2 J3.2
A2: length 2.8
  TOP w0.127: R81.2 J3.3
A3: length 2.8
  TOP w0.127: R80.2 J3.4
A4: length 2.8
  TOP w0.127: R85.1 J3.5
A5: length 2.8
  TOP w0.127: R84.1 J3.6
D2: length 32.2
  TOP w0.127: v1(57.1,40.78) 46.98,50.89 J1.3
  BOTTOM w0.127: v1(57.1,40.78) 59.26,38.62 63.61,38.62 J72.2
D3: length 35.9
  TOP w0.127: v1(57.13,38.14) 44.44,50.83 J1.4
  BOTTOM w0.127: v1(57.13,38.14) 59.2,36.07 63.6,36.07 J68.2
D4: length 38.6
  TOP w0.127: J1.5 41.9,50.89 v1(57.11,35.68)
  BOTTOM w0.127: J69.2 63.52,35.69 57.58,35.69 57.58,35.68 v1(57.11,35.68)
D5: length 43
  TOP w0.127: v1(57.3,33.02) 39.36,50.96 J1.6
  BOTTOM w0.127: J78.2 63.57,30.96 59.36,30.96 v1(57.3,33.02)
D6: length 45.7
  TOP w0.127: J1.7 36.82,50.98 v1(57.28,30.52)
  BOTTOM w0.127: v1(57.28,30.52) 57.73,30.52 57.74,30.53 60.01,30.53 60.02,30.53 63.6,30.53 J80.2
D7: length 50.2
  TOP w0.127: v1(57.3,27.86) 34.28,50.88 J1.8
  BOTTOM w0.127: v1(57.3,27.86) 59.29,25.88 63.57,25.88 J83.2
D8: length 53.5
  TOP w0.127: J2.1 30.22,52.55 v1(57.33,25.44)
  BOTTOM w0.127: v1(57.33,25.44) 63.61,25.44 J82.2
D9: length 56.8
  TOP w0.127: v1(57.43,23.28) 27.68,53.03 J2.2
  BOTTOM w0.127: v1(57.43,23.28) 63.23,23.28 J71.2
D10/SPI_CS: length 62
  TOP w0.127: J2.3 26.92,61.75 71.95,61.75 74.44,59.26 79.27,59.26 79.27,59.26 v1(79.75,59.26)
  BOTTOM w0.127: v1(79.75,59.26) 80.7,59.26 81.53,58.42 J74.2 J70.2
D11/SPI_MOSI: length 69.4
  TOP w0.127: v1(76.43,59.81) 74.74,59.81 72.3,62.26 24.89,62.26 J2.4
  BOTTOM w0.127: v1(76.43,59.81) 76.43,52.11 77.28,51.26 80.44,51.26 J73.2
D12/SPI_MISO: length 76.4
  TOP w0.127: J2.5 22.85,62.76 72.89,62.76 74.72,60.93 v1(75.91,60.93)
  BOTTOM w0.127: v1(75.91,60.93) 75.91,49.64 77.19,48.36 81.07,48.36 81.53,48.82 J81.2
D13/SPI_CLK: length 81.2
  TOP w0.127: J2.6 20.82,63.27 73.78,63.27 v1(74.95,62.1)
  BOTTOM w0.127: v1(74.95,62.1) 74.62,61.77 74.62,48.92 77.52,46.02 80.28,46.02 J65.2
D14/I2C_SDA: length 92.9
  TOP w0.127: v1(73.5,18.49) 59.63,18.49 20.82,57.3 12.57,57.3 J2.9
  BOTTOM w0.127: v1(73.5,18.49) 78.34,18.49 80.5,20.65 80.5,22.43 81.53,23.46 J64.2
D15/I2C_SCL: length 94.3
  TOP w0.127: J2.10 10.66,56.67 20.7,56.67 59.75,17.61 73.85,17.61 73.86,17.61 v1(74.3,17.61)
  BOTTOM w0.127: J66.2 81.53,20.48 78.66,17.61 v1(74.3,17.61)
ELE_PS_SENSE: length 176.1
  TOP w0.635: J16.B4 83.5,73.41 83.31,73.22 83.31,72.01 v1(84.3,71.02) ; J16.D4 6.5,7.61 5.79,8.32 v1(5.72,8.32) 17.77,20.38 D16.C
  BOTTOM w0.635: v1(5.72,8.32) 6.95,9.55 16.55,9.55 18.71,7.39 75.66,7.39 88.36,20.09 88.36,66.95 v1(84.3,71.02)
GPIO/D2: length 44
  TOP w0.127: v1(64.5,72.95) 64.5,73.39 J16.B21
  BOTTOM w0.127: v1(64.5,72.95) 64.5,68.21 71.34,61.37 71.34,49.85 62.1,40.6 J72.1
GPIO/D3: length 48.8
  TOP w0.127: v1(63.51,73.96) 63.51,74.4 63.5,74.41 J16.B22
  BOTTOM w0.127: v1(63.51,73.96) 64.43,73.96 65.09,73.3 65.09,68.41 71.75,61.75 71.75,46.34 65.67,40.26 65.67,39.1 64.71,38.14 63.13,38.14 J68.3
GPIO/D4: length 57.8
  TOP w0.127: v1(71.5,37.41) v1(75.09,37.41)
  BOTTOM w0.127: J69.1 62.1,34.37 62.92,33.54 69.22,33.54 71.5,35.81 v1(71.5,37.41) ; J16.A9 78.5,72.81 74.24,68.55 74.24,38.26 v1(75.09,37.41)
GPIO/D5: length 58.9
  TOP w0.127: J16.B23 v1(62.5,74.48)
  BOTTOM w0.127: J78.3 63.17,33.1 69.74,33.1 73.07,36.43 73.07,65.86 64.45,74.48 v1(62.5,74.48)
GPIO/D6: length 97.7
  TOP w0.127: v1(72.18,30.11) 72.98,30.91 80.36,30.91 87.6,38.15 87.6,59.39 76.4,70.59 53.32,70.59 50.5,73.41 J16.B35
  BOTTOM w0.127: v1(72.18,30.11) 70.53,28.46 63.13,28.46 J80.3
GPIO/D7: length 61.7
  BOTTOM w0.127: J83.1 63.13,27.98 72.02,27.98 73.86,29.82 73.86,48.6 73.85,48.61 73.85,68.7 77.5,72.35 J16.A10
GPIO/D8: length 66.3
  TOP w0.127: v1(73.14,30.15) 73.14,24.57 v1(71.75,23.18)
  BOTTOM w0.127: v1(73.14,30.15) 73.48,30.49 73.48,48.45 73.47,48.46 73.47,68.86 76.83,72.22 76.83,73.94 76.5,74.27 J16.A11 ; v1(71.75,23.18) 64.28,23.18 63.05,24.41 J82.1
GPIO/D9: length 90.3
  TOP w0.127: J16.B52 33.54,76.98 v1(33.54,74.15)
  BOTTOM w0.127: J71.3 55.06,14.83 39.37,14.83 38.12,16.08 38.12,69.58 v1(33.54,74.15)
I2C0_SCL/D15: length 60.9
  BOTTOM w0.127: J66.1 80.39,23.27 80.39,39.91 86.71,46.23 86.71,61.01 82.49,65.23 82.49,72.54 80.5,74.54 J16.A7
I2C0_SDA/D14: length 58.5
  BOTTOM w0.127: J16.A8 79.5,74.87 81.94,72.43 81.94,64.74 86.33,60.35 86.33,46.99 78.99,39.65 J64.1
I2C1_SCL/D15: length 128.8
  TOP w0.127: J16.B50 35.5,71.47 33.68,69.65 18.44,69.65 13.63,64.84 13.63,59.52 14.57,58.57 21.33,58.57 59.81,20.09 71.25,20.09 71.26,20.09 v1(71.7,20.09)
  BOTTOM w0.127: J66.3 84.07,20.76 79.24,15.93 72.97,15.93 71.7,17.19 v1(71.7,20.09)
I2C1_SDA/D14: length 132.3
  TOP w0.127: J16.B51 34.5,72.19 32.93,70.62 17.68,70.62 11.21,64.15 11.21,59.55 12.82,57.94 21.1,57.94 59.71,19.33 72.09,19.33 72.1,19.33 v1(72.54,19.33)
  BOTTOM w0.127: v1(72.54,19.33) 72.54,17.5 73.32,16.71 78.76,16.71 82.85,20.8 82.85,23.19 J64.3
PWM/D2: length 63
  TOP w0.127: v1(67.97,66.65) 49.76,66.65 45.22,71.19 45.22,74.59 45.5,74.87 J16.B40
  BOTTOM w0.127: v1(67.97,66.65) 72.13,62.48 72.13,41.71 70.07,39.65 J72.3
PWM/D3: length 65.2
  TOP w0.127: v1(45.8,74.37) 45.8,71.7 50.13,67.36 68.6,67.36 v1(69.21,66.75)
  BOTTOM w0.127: J68.1 68.98,37.11 72.51,40.64 72.51,63.45 v1(69.21,66.75) ; v1(45.8,74.37) 45.5,74.67 J16.A40
PWM/D4: length 86.6
  TOP w0.127: J16.B39 46.5,74.28 46.22,74.01 46.22,72.16 50.52,67.87 76.02,67.87 85.36,58.52 85.36,43.58 77.9,36.12 v1(70.68,36.12)
  BOTTOM w0.127: v1(70.68,36.12) 69.13,34.57 J69.3
PWM/D5: length 88.4
  TOP w0.127: v1(72.56,34.93) 73.01,34.93 73.01,34.94 77.96,34.94 85.9,42.88 85.9,58.6 76.09,68.4 50.93,68.4 v1(46.77,72.57)
  BOTTOM w0.127: v1(46.77,72.57) 46.77,74.14 46.5,74.41 J16.A39 ; J78.1 69.66,32.03 v1(72.56,34.93)
PWM/D6: length 90.2
  TOP w0.127: v1(47.54,73.74) 47.54,72.65 51.21,68.99 76.07,68.99 86.35,58.7 86.35,41.69 77.97,33.3 72.99,33.3 72.99,33.3 v1(72.54,33.3)
  BOTTOM w0.127: J16.A38 47.5,74.23 47.54,74.18 v1(47.54,73.74) ; J80.1 68.73,29.49 v1(72.54,33.3)
PWM/D7: length 94.2
  TOP w0.127: J16.B38 47.5,74.56 48.11,73.95 48.11,73.34 51.9,69.55 76.14,69.55 86.74,58.95 86.74,40.64 78.38,32.28 72.16,32.28 70.44,30.57 v1(70.44,26.95)
  BOTTOM w0.127: J83.3 67.18,26.95 v1(70.44,26.95)
PWM/D8: length 97.1
  TOP w0.127: J16.B37 48.5,74.08 52.52,70.05 76.27,70.05 87.12,59.21 87.12,39.27 79.31,31.47 72.41,31.47 71.1,30.16 v1(71.1,24.41)
  BOTTOM w0.127: v1(71.1,24.41) J82.3
PWM/D9: length 126.8
  BOTTOM w0.127: J16.A37 48.5,73.14 50.24,71.4 55.16,71.4 68.3,58.27 68.3,53.49 64.49,49.68 49.17,49.68 38.76,39.27 38.76,15.99 39.41,15.33 53.86,15.33 61.42,22.9 62.72,22.9 63.34,22.28 63.34,21.66 64.22,20.78 66.09,20.78 J71.1
RESET_B: length 26.1
  TOP w0.127: R79.2 v1(25.34,35.38)
  BOTTOM w0.127: J4.3 23.11,13.23 23.11,33.15 v1(25.34,35.38)
SPI0_CS0/D10: length 53.3
  TOP w0.127: J16.B47 38.5,72.27 46.4,64.36 74.8,64.36 77.05,62.11 v1(77.52,62.11)
  BOTTOM w0.127: J74.1 78.99,60.64 v1(77.52,62.11)
SPI0_CS1/D10: length 55
  TOP w0.127: v1(76.67,63.54) 75.31,64.9 47.14,64.9 39.5,72.54 J16.B46
  BOTTOM w0.127: v1(76.67,63.54) 76.67,61.51 77.52,60.65 77.52,56.35 J70.1
SPI0_MISO/D12: length 63.2
  TOP w0.127: J16.B44 41.5,73.54 48.94,66.09 77,66.09 v1(78.67,64.41)
  BOTTOM w0.127: J81.1 80.06,50.88 81.84,50.88 82.56,51.61 82.56,58.68 78.67,62.57 v1(78.67,64.41)
SPI0_MOSI/D11: length 57.2
  TOP w0.127: v1(76.15,64.98) 75.59,65.53 48.15,65.53 40.5,73.19 J16.B45
  BOTTOM w0.127: v1(76.15,64.98) 76.15,61.43 77.04,60.54 77.04,53.34 78.04,52.35 J73.1
SPI0_SCK/D13: length 65.1
  TOP w0.127: J16.B48 37.5,72 45.69,63.8 74.52,63.8 v1(75.53,62.79)
  BOTTOM w0.127: v1(75.53,62.79) 75.53,61.52 75.22,61.2 75.22,49.23 77.19,47.27 J65.1
SPI1_CS0/D10: length 21.9
  TOP w0.127: v1(79.04,72.75) 78.5,73.29 J16.B9
  BOTTOM w0.127: J74.3 84.07,58.85 79.6,63.32 79.6,72.19 v1(79.04,72.75)
SPI1_CS1/D10: length 25.2
  TOP w0.127: J16.B8 79.5,74.77 v1(79.09,74.36)
  BOTTOM w0.127: v1(79.09,74.36) 79.09,73.43 80.08,72.44 80.08,63.68 85.11,58.65 85.11,55.93 J70.3
SPI1_MISO/D12: length 30.9
  TOP w0.127: v1(78.15,71.53) 77.07,72.6 77.07,74.28 76.5,74.85 J16.B11
  BOTTOM w0.127: J81.3 83.12,49.81 82.95,49.98 82.95,59.13 79.19,62.89 79.19,70.48 v1(78.15,71.53)
SPI1_MOSI/D11: length 29.5
  TOP w0.127: J16.B10 77.5,73.5 79.19,71.81 v1(80.77,71.81)
  BOTTOM w0.127: J73.3 85.52,53.8 85.52,59.26 80.77,64.01 v1(80.77,71.81)
SPI1_SCK/D13: length 34.2
  TOP w0.127: J16.B7 80.5,74.12 v1(79.82,73.44)
  BOTTOM w0.127: J65.3 85.02,47.27 85.95,48.2 85.95,59.94 81.5,64.39 81.5,72.29 80.35,73.44 v1(79.82,73.44)
UART0_RX/D0: length 28.2
  BOTTOM w0.127: J67.1 59.81,57.43 44.5,72.74 J16.A41
UART0_TX/D1: length 30.4
  BOTTOM w0.127: J16.A42 43.5,72.54 61.15,54.89 J63.1
UART1_RX/D0: length 46.8
  BOTTOM w0.127: J67.3 66.03,56.29 66.03,54.39 63.72,52.07 53.06,52.07 48.1,57.02 48.1,66.98 42.5,72.58 J16.A43
UART1_TX/D1: length 46.8
  BOTTOM w0.127: J63.3 63.8,51.51 51.35,51.51 45.66,57.2 45.66,68.53 41.5,72.69 J16.A44
UART_RX/D1: length 20.4
  BOTTOM w0.127: J63.2 62.5,52.76 54.35,52.76 49.52,57.58 J1.2
UART_TX/D0: length 19.7
  BOTTOM w0.127: J1.1 52.06,57 55.49,53.57 62.68,53.57 63.5,54.39 63.5,56.29 J67.2
VREF: length 8.6
  TOP w0.635: R78.2 14.57,62.55 v1(14.57,61.74)
  L3_PWR w0.381: TP5.1 19.04,67.18 ; TP5.1 19.04,65.3 ; TP5.1 18.1,66.24 ; TP5.1 19.99,66.24 ; 12.44,58.95 J2.8 ; J2.8 12.44,60.99 ; J2.8 13.46,59.97 ; J2.8 11.42,59.97
N13251626: length 80.3
  TOP w0.127: J16.B29 56.5,73.96 57.98,72.48 60.03,72.48 v1(60.75,71.75) ; R84.2 v1(52.06,16.28)
  BOTTOM w0.127: v1(52.06,16.28) 52.06,37.85 59.74,45.52 66.19,45.52 70.91,50.24 70.91,60.97 60.75,71.13 v1(60.75,71.75)
N13251632: length 82.1
  TOP w0.127: J16.B30 55.5,73.88 57.53,71.85 v1(59.12,71.85) ; R85.2 v1(49.52,16.28)
  BOTTOM w0.127: v1(59.12,71.85) 70.51,60.46 70.51,50.88 66.01,46.38 57.96,46.38 49.52,37.95 v1(49.52,16.28)
N13255265: length 81.7
  TOP w0.127: R80.1 v1(46.98,16.28)
  BOTTOM w0.127: J16.A27 58.5,71.46 70.05,59.91 70.05,51.31 65.88,47.14 55.93,47.14 46.98,38.2 v1(46.98,16.28)
N13255295: length 83.6
  TOP w0.127: R81.1 v1(44.44,16.28)
  BOTTOM w0.127: v1(44.44,16.28) 44.44,38 54.22,47.78 65.53,47.78 69.62,51.87 69.62,59.66 57.5,71.78 J16.A28
N13255352: length 85.6
  TOP w0.127: R82.1 v1(41.9,16.28)
  BOTTOM w0.127: J16.A29 56.5,71.82 69.18,59.14 69.18,52.35 65.25,48.41 52.4,48.41 41.9,37.92 v1(41.9,16.28)
N13255371: length 87.4
  TOP w0.127: R83.1 v1(39.36,16.28)
  BOTTOM w0.127: J16.A30 55.5,71.94 68.73,58.71 68.73,52.93 64.84,49.05 50.69,49.05 39.36,37.72 v1(39.36,16.28)
N13256362: length 35
  TOP w0.127: R78.1 15.58,64.76 19.58,68.76 37.74,68.76 v1(38.85,69.87)
  BOTTOM w0.127: v1(38.85,69.87) 39.5,70.52 J16.A46
N13260720: length 41.3
  TOP w0.127: R79.1 v1(25.34,38.02)
  BOTTOM w0.127: J16.A62 23.5,69.31 26.28,66.52 26.28,38.96 v1(25.34,38.02)
N13275722: length 11.1
  TOP w0.127: R86.1 v1(40.5,66.76)
  BOTTOM w0.127: J16.A45 v1(40.5,66.76)

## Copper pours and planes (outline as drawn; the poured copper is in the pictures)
3V3_ELEV on TOP: 2.87,45.39 3.14,45.67 6.47,45.67 6.62,45.52 6.62,43.56 16.38,43.57 16.38,41.28 6.95,41.28 6.95,39.5 6.73,39.27 3.02,39.27 2.87,39.42
3V3_ELEV on TOP: 17.67,15.23 17.67,7.68 25.42,7.68 25.42,15.23
3V3_ELEV on L3_PWR: 37.33,8.41 37.33,37 13.21,37 13.21,43.97 24.27,43.97 24.27,50.31 22.09,50.31 22.09,68.1 1.14,68.1 1.14,69.37 3.04,69.37 4.31,70.64 4.31,72.92 3.49,73.75 3.49,78.26 73.42,78.26 73.42,72.65 73.47,72.65 75.05,71.4 76.63,72.65 76.7,72.65 76.7,78.26 86.35,78.26 86.35,74.51 85.06,74.51 84.73,74.18 84.73,72.33 83.05,72.33 83.05,65.48 86.84,61.7 86.84,45.59 83.33,42.09 83.33,27.58 85.54,25.37 85.54,19.76 79.8,14.02 70.4,14.02 70.35,13.97 70.35,7.85 70.43,7.77 86.23,7.77 86.23,2.06 17.01,2.06 17.01,8.41 16.17,9.25 14.04,9.25 13.2,8.41 13.2,2.06 3.68,2.06 3.68,7.77 5.58,7.77 5.58,12.01 4.9,12.7 4.9,14.88 5.58,15.57 5.58,20.47 21.46,20.47 21.46,14.2 20.31,14.2 20.31,8.41
5V_ELEV on TOP: 25.53,7.59 84.6,7.59 84.6,13.92 53.31,13.92 53.35,13.88 53.35,10.57 53.19,10.41 37.86,10.41 37.9,10.45 37.9,13.92 30.98,13.92 30.98,27.1 19.38,27.1 19.38,16.16 25.53,16.16
5V_ELEV on L3_PWR: 1.14,26.82 21.46,26.82 21.46,21.11 5.33,21.11 4.95,20.72 4.95,15.57 4.52,15.14 4.52,12.42 4.95,11.99 4.95,8.41 3.75,8.41 3.75,11.58 1.14,11.58
5V_ELEV on L3_PWR: 86.86,69.37 88.77,69.36 88.77,11.58 87.5,11.58 86.23,10.31 86.23,8.41 70.99,8.41 70.99,13.51 80.03,13.51 86.08,19.56 86.08,25.58 84.04,27.61 84.04,41.96 87.42,45.34 87.42,61.98 83.66,65.74 83.66,71.86 83.71,71.81 85.38,71.81 85.38,74.23 86.41,74.23 86.41,69.82
GND on L2_GND: 3.75,1.55 3.75,11.58 1.14,11.58 1.14,69.49 3.04,69.49 3.68,70.14 3.68,79.02 72.76,79.02 72.76,73.3 75.03,70.95 77.3,73.3 77.3,79.02 86.35,79.02 86.35,69.88 86.87,69.36 88.77,69.37 88.73,11.58 87.5,11.58 86.24,10.32 86.2,1.55 17.3,1.58 17.3,7.4 15.03,9.75 12.76,7.4 12.76,1.55 ; 2 cut-outs
P5V_VREG on TOP: 22.78,32.79 23.11,32.46 23.11,27.97 16.68,27.97 12.62,23.9 4.31,23.9 2.97,25.25 2.97,32.54 3.22,32.79
VIN on TOP: 12.57,49.05 18.92,49.05 18.92,46.51 24,46.51 24,52.22 12.57,52.22
VIN on L3_PWR: 1.14,55.4 1.14,27.45 22.09,27.45 22.09,14.76 20.96,14.76 20.96,9.04 36.69,9.04 36.7,36.35 12.58,36.35 12.58,44.61 23.62,44.61 23.62,49.67 21.46,49.67 21.46,55.4
VREF on L3_PWR: 1.14,67.65 21.47,67.63 21.47,56.03 1.14,56.03

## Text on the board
BOTTOM: 170-28111 REV B | 7 OF 9 | L4_SS
Board Geometry/Soldermask Bottom: 8 OF 9 | SECONDARY SOLDERMASK
Package Geometry/Pastemask Bottom: SECONDARY SOLDERPASTE | 10 OF 10
Ref Des/Silkscreen Bottom: 9 OF 9 | SECONDARY SILKSCREEN
TOP: 4 OF 9 | L1_PS
Board Geometry/Soldermask Top: 3 OF 9 | PRIMARY SOLDERMASK
Package Geometry/Pastemask Top: 1 OF 9 | PRIMARY SOLDERPASTE
Ref Des/Silkscreen Top: 3V3_REG | 5V_REG | TX | RX | D2 | D8 | D3 | D4 | D5 | D7 | D6 | D9 | MISO | MOSI | CS0 | CLK | CS1 | SDA | SCL | D15/I2C_SCL | D14/I2C_SDA | VREF | GND | D13/SPI | 3V3 | D12/SPI_MISO | RST | D11/SPI_MOSI | D10/SPI_CS | 5V | VIN | A5 | A4 | A3 | A2 | UART_RX/D1 | A1 | UART_TX/D0 | A0 | UART0 | GPIO | D2-D9 | D0-D1 | UART1 | PWM | SPI0 | I2C0 | D14-D15 | D10-D13 | SPI1 | I2C1 | 2 OF 9 | PRIMARY SILKSCREEN | TWR-SHIELD
L2_GND: 5 OF 9 | L2_GND
L3_PWR: 6 OF 9 | L3_PWR
DIMENSION: R .031 | 4 PL | 0.394 | 0.472 | 0.059 | 0.028 | 0.039 | 2.835 | 2.756 | 8 PL | CHAMFERED | R0.039 | 0.338 | 0.219 | 0.126 | 0.155 | 0.093 | GRID ORIGIN | PRIMARY DATUM | ALL ELEVATOR MODULES ARE BLACK | WITH WHITE "TOWER" SILKSCREEN | (4X) | "+/-.005" | 4 pl | 22. INTENTIONAL SHORTS AT: | J20   VIN_HDR & VIN | THE ADDITION OF RAILS AND .125"NON-PLATED TOOLING HOLES ARE AT THE DISCRETION OF | J69   GPIO/D4 & D4 | J67   UART0_RX/D0 & UART_TX/D0 | J73   SPI0_MOSI/D11 & D11/SPI_MOSI | J81   SPI0_MISO/D12 & D12/SPI_MISO | J65   SPI0_SCK/D13 & D13/SPI_CLK | J63   UART0_TX/D1 & UART_RX/D1 | J68   PWM/D3 & D3 | J82   GPIO/D8 & D8 | J74   SPI0_CS0/D10 & D10/SPI_CS | J64   I2C0_SDA/D14 & D14/I2C_SDA | J66   I2C0_SCL/D15 & D15/I2C_SCL | J72   GPIO/D2 & D2 | J78   PWM/D5 & D5 | J80   PWM/D6 & D6 | J83   GPIO/D7 & D7 | J71   PWM/D9 & D9 | CONTRACT MANUFACTURER.PANELIZATION MUST BE APPROVED BY CONTRACT MANUFACTURER. | 16 | b. THE PCI CARD EDGE CONNECTOR GOLD FINGERS, PLATING REQUIREMENTS: | 30U OVER HARD GOLD OVER 100~200U NICKEL BOTH SIDES OF THE BOARD. | 7b | 17 | SECONDARY | CONNECTOR | PRIMARY | DETAILS OF pci-e CONNECTOR COMPONENT | SIDE | I/O PANEL DIRECTION | DETAILS OF pci-e CONNECTOR SOLDER SIDE | B1 | A1 | DETAIL C | 8 | VIEW FROM PRIMARY SIDE
User.8: [MM] | 12-04-13 | B.F. | B | PER ECO47615 | 1
User.17: 0.062 | 3.543 | 3.481 | 0.236 | 0.138 | 0.172 | 1.116 | 0.555 | 0.157 | 0.591 | 1.700 | 1.163 | 0.728 | 0.850 | 3.541 | MAXIMUM | COMPONENT | HEIGHT | PRIMARY | elevator | SECONDARY | TOP SIDE | BOT SIDE
User.18: ZONE | REV | DESCRIPTION | 05/14/09 | 08/31/09 | 10/28/10 | 09/21/09 | 09/27/11 | 11/02/11 | DATE | APPROVED | FIX DIMENSION ERROR ADDED COLOR INFORMATION | FIX DIMENSION ERROR & ADD DETAIL INFO ON DRAWING | ALVIN.D | D. K. | L. S. | A | B | D | C | E | F | ADDED .031 RADIUS 4 PL | PROTOTYPE RELEASE | ADD DETAILED PCI-E CONNECTOR INFO | ADD DETAILED INFO FOR J8&J9 | TOWER TEMPLATE REVISIONS PER 900-76126
User.19: FIGURE | SIZE | 10.0 | 40.0 | 41.0 | 25.0 | DRILL CHART: TOP to BOTTOM | ALL UNITS ARE IN MILS | TOLERANCE | +0.0/-10.0 | +3.0/-3.0 | +2.0/-2.0 | PLATED | NON-PLATED | QTY | 107 | 84 | 6 | 1
